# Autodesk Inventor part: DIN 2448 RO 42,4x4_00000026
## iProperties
Created: 2006-02
Part Number: DIN 2448 RO 42,4x4_00000026
Material: Default
Document SubType Name: Modeling
Designer: FranzK
Stock Number: DIN 2448 RO 42,4x4
Mass: 421.966 g
Surface Area: 2123.47 cm^2
Volume: 421.966 cm^3
Density: 1 g/cm^3
G_L: 890.000 mm
G_W: 42.400 mm
G_H: 42.400 mm
AFG_Item: 42.4 x 4
CSToolsMass: 0.4
CSToolsVolume: 421966.0
CSToolsArea: 2123.0
Author: FranzK
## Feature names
1. AFG_Detailed_DIN 2448 RO 42,4x4_00000026 [Extrusion]
2. AFG_Simplified_DIN 2448 RO 42,4x4_00000026 [Extrusion]
3. AFG_StartExtrusion_1 [Extrusion]
4. AFG_StartExtrusion_2 [Extrusion]
